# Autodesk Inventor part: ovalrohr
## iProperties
Created: 2005-06
Part Number: ovalrohr
Document SubType Name: Modeling
Designer: schumann
Material: Stahl
Author: schumann
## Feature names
1. Extrusion1
2. Extrusion2
3. Extrusion3
4. Extrusion4
